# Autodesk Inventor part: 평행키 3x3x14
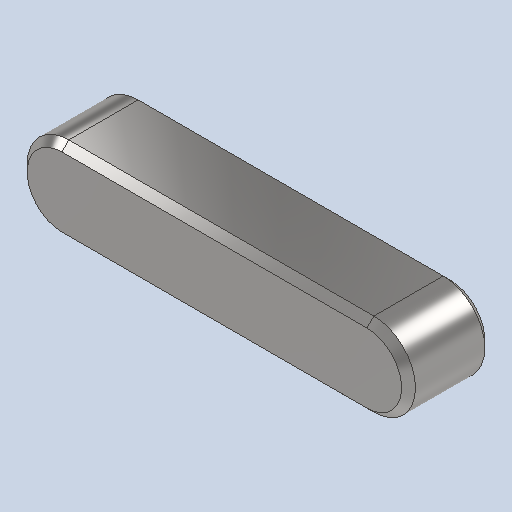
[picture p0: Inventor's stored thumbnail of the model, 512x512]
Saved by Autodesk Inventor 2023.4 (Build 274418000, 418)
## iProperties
Created: 2024-09
Part Number: 평행키 3x3x14
Material: 강철, 연강
Description: 키 및 해당 키홈
Document SubType Name: Modeling
Designer: EDU
Density: 7.85 g/cm^3
Appearance: 기본값
Author: jhkim
Sending System: Autodesk Inventor 2025
Preprocessor: ST-DEVELOPER v20
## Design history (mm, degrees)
feature "Solid1"
node "솔리드1"
